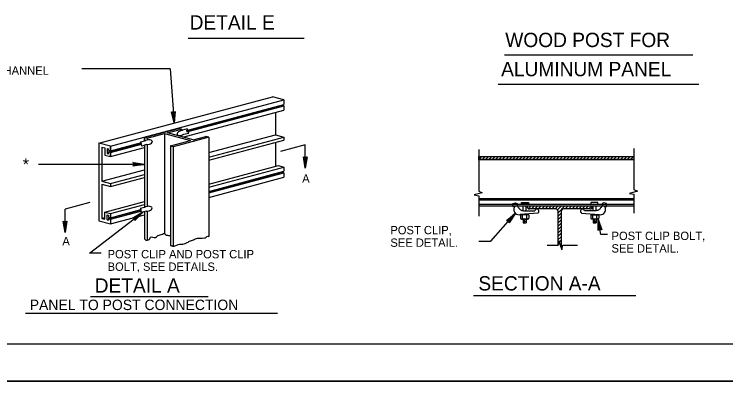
# Model space of a CAD drawing. Extents: x -4 to 901, y -468 to 720.
# Drawn here: x 303.3 to 589.7, y 118.5 to 273.7 of the extents above; entities that cross this region are included whole.
import ezdxf

# ---------------------------------------------------------------- set-up
doc = ezdxf.new("R2010")
doc.units = 0
for name, color, linetype in [('1', 7, 'Continuous'), ('2', 7, 'Continuous'), ('3', 7, 'Continuous'), ('PLT-BNDY', 7, 'Continuous')]:
    doc.layers.add(name, color=color, linetype=linetype)

msp = doc.modelspace()

# ---------------------------------------------------------------- linework, layer by layer
at = {"layer": '1'}
msp.add_lwpolyline([(822.258, 141.027875), (822.258, 705.027875), (36.258, 705.027875), (36.258, 141.027875), (822.258, 141.027875), (822.258, 167.386875), (622.258, 167.386875), (622.258, 232.064375), (822.258, 232.064375), (822.258, 261.027875), (622.258, 261.027875), (622.258, 141.027875), (701.0595, 141.027875), (701.0595, 167.386875), (701.0595, 141.027875), (778.0595, 141.027875), (778.0595, 167.386875), (778.0595, 155.070375), (822.258, 155.070375)], dxfattribs=at)
at = {"layer": '2'}
for p, q in [((365.98, 251.736375), (330.525, 251.736375)), ((365.98, 251.736375), (367.605, 229.949625)), ((337.339, 221.803625), (407.157, 240.509625)), ((341.975, 220.561625), (411.793, 239.267625)), ((411.793, 239.267625), (407.157, 240.511625)), ((411.793, 239.267625), (411.793, 237.425625)), ((371.165, 224.277625), (411.793, 235.163625)), ((372.565, 226.913625), (411.793, 237.425625)), ((372.615, 226.775625), (410.959, 237.049625)), ((372.767, 226.367625), (411.793, 236.825625)), ((410.959, 237.049625), (411.793, 236.825625)), ((411.793, 236.825625), (411.793, 235.163625)), ((408.357, 234.241625), (408.357, 225.209625)), ((363.743, 226.265625), (369.405, 227.783625)), ((370.563, 227.471625), (369.405, 227.783625)), ((370.563, 227.471625), (370.563, 226.749625)), ((372.879, 227.531625), (370.985, 227.011625)), ((373.493, 225.845625), (372.879, 227.531625)), ((355.629, 224.091625), (355.629, 222.595625)), ((356.787, 223.781625), (355.629, 224.091625)), ((363.743, 225.645625), (363.743, 185.465625)), ((371.571, 225.403625), (373.493, 225.845625)), ((381.595, 224.217625), (380.437, 224.527625)), ((381.595, 218.037625), (408.357, 225.209625)), ((381.595, 216.197625), (411.793, 224.289625)), ((408.357, 225.209625), (411.793, 224.289625)), ((411.793, 224.289625), (411.793, 223.047625)), ((341.975, 220.561625), (337.339, 221.803625)), ((337.339, 221.803625), (337.339, 190.603625)), ((341.141, 218.341625), (354.563, 221.937625)), ((341.141, 218.341625), (354.345, 221.875625)), ((341.975, 218.717625), (354.425, 222.053625)), ((341.975, 218.117625), (354.495, 221.471625)), ((341.975, 220.561625), (341.975, 218.717625)), ((341.975, 218.717625), (341.975, 220.559625)), ((354.261, 222.409625), (356.161, 222.907625)), ((354.573, 220.643625), (354.261, 222.409625)), ((356.457, 221.221625), (354.573, 220.643625)), ((355.629, 221.059625), (355.629, 195.795625)), ((367.261, 220.375625), (366.103, 220.685625)), ((381.595, 214.955625), (411.793, 223.047625)), ((408.357, 222.125625), (408.357, 212.435625)), ((420.383, 221.185625), (410.405, 218.511625)), ((420.383, 211.785625), (420.383, 221.185625)), ((338.539, 220.239625), (338.539, 206.501625)), ((338.539, 220.239625), (339.767, 219.909625)), ((339.767, 219.909625), (339.767, 217.047625)), ((340.601, 219.685625), (340.601, 217.687625)), ((340.601, 219.685625), (341.141, 219.541625)), ((340.601, 217.687625), (341.161, 217.837625)), ((340.601, 217.687625), (341.141, 217.543625)), ((341.141, 218.941625), (341.141, 219.541625)), ((341.141, 218.941625), (341.975, 218.717625)), ((341.141, 217.543625), (341.141, 218.341625)), ((341.141, 218.341625), (341.975, 218.117625)), ((341.975, 216.455625), (355.629, 220.113625)), ((341.975, 218.117625), (341.975, 216.455625)), ((341.975, 216.455625), (341.975, 218.117625)), ((490.19325, 219.327875), (490.19325, 202.533875)), ((552.59325, 219.731875), (552.59325, 203.185875)), ((339.767, 217.047625), (341.975, 216.455625)), ((490.19325, 216.407875), (519.02325, 216.407875)), ((490.19325, 215.207875), (519.02325, 215.207875)), ((519.02325, 216.407875), (528.28125, 216.407875)), ((519.02325, 215.207875), (528.28125, 215.207875)), ((528.28125, 216.407875), (552.59325, 216.407875)), ((528.28125, 215.207875), (552.59325, 215.207875)), ((355.629, 213.296125), (312.982, 213.296125)), ((381.595, 205.265625), (409.585, 212.765625)), ((381.595, 204.081625), (411.793, 212.173625)), ((409.585, 212.765625), (411.793, 212.173625)), ((411.793, 212.173625), (411.793, 210.511625)), ((338.539, 206.501625), (355.629, 211.081625)), ((341.975, 205.581625), (355.629, 209.239625)), ((381.595, 202.417625), (411.793, 210.511625)), ((381.595, 202.267625), (410.959, 210.133625)), ((381.595, 201.817625), (411.793, 209.911625)), ((411.793, 209.911625), (410.959, 210.133625)), ((411.793, 209.911625), (411.793, 208.067625)), ((338.539, 206.501625), (341.975, 205.581625)), ((341.975, 204.339625), (355.629, 207.997625)), ((381.595, 199.977625), (411.793, 208.067625)), ((338.539, 205.259625), (341.975, 204.339625)), ((338.539, 205.259625), (338.539, 191.523625)), ((341.975, 205.581625), (341.975, 204.339625)), ((490.19325, 200.651875), (490.19325, 192.405875)), ((552.59325, 201.279875), (552.59325, 193.643875)), ((333.697, 197.957625), (323.719, 195.283625)), ((339.767, 194.057625), (355.629, 198.307625)), ((490.19325, 199.607875), (519.02325, 199.607875)), ((490.19325, 199.007875), (519.02325, 199.007875)), ((519.02325, 199.607875), (528.28125, 199.607875)), ((519.02325, 199.007875), (528.28125, 199.007875)), ((528.28125, 199.607875), (552.59325, 199.607875)), ((528.28125, 199.007875), (552.59325, 199.007875)), ((323.719, 185.883625), (323.719, 195.283625)), ((341.141, 191.427625), (354.395, 194.977625)), ((341.141, 191.427625), (354.379, 194.971625)), ((341.975, 193.465625), (355.629, 197.123625)), ((341.975, 191.803625), (354.241, 195.089625)), ((354.151, 195.635625), (356.051, 196.131625)), ((354.463, 193.867625), (354.151, 195.635625)), ((490.19325, 197.207875), (519.02325, 197.207875)), ((490.19325, 196.607875), (519.02325, 196.607875)), ((508.08125, 194.639875), (508.08125, 196.593875)), ((509.36925, 194.627875), (509.36925, 196.523875)), ((509.60325, 196.415875), (509.60325, 196.535875)), ((509.60325, 196.535875), (536.00325, 196.535875)), ((519.02325, 197.207875), (528.28125, 197.207875)), ((519.02325, 196.607875), (528.28125, 196.607875)), ((528.28125, 197.207875), (552.59325, 197.207875)), ((528.28125, 196.607875), (552.59325, 196.607875)), ((536.00325, 196.535875), (536.00325, 196.415875)), ((536.23925, 194.627875), (536.23925, 196.523875)), ((537.52525, 194.639875), (537.52525, 196.593875)), ((339.767, 194.057625), (341.975, 193.465625)), ((339.767, 191.195625), (339.767, 194.057625)), ((340.601, 190.971625), (340.601, 192.969625)), ((340.601, 192.969625), (341.141, 192.823625)), ((341.141, 192.823625), (341.141, 192.027625)), ((341.141, 192.027625), (341.975, 191.803625)), ((341.975, 191.203625), (354.269, 194.497625)), ((341.975, 193.465625), (341.975, 191.803625)), ((341.975, 189.361625), (355.629, 193.019625)), ((356.347, 194.445625), (354.463, 193.867625)), ((355.629, 194.267625), (355.629, 183.291625)), ((514.00325, 193.653875), (506.93525, 193.087875)), ((507.04525, 193.033875), (507.04525, 191.569875)), ((510.32725, 193.033875), (507.04525, 193.033875)), ((510.20925, 193.119875), (507.16925, 193.119875)), ((507.16925, 193.041875), (507.16925, 193.119875)), ((507.85325, 191.589875), (507.85325, 193.033875)), ((508.24125, 194.637875), (512.85325, 194.599875)), ((509.51925, 191.599875), (509.51925, 193.033875)), ((510.20925, 193.041875), (510.20925, 193.119875)), ((510.32725, 193.033875), (510.32725, 191.577875)), ((531.60325, 193.653875), (538.67325, 193.087875)), ((537.36725, 194.637875), (532.75325, 194.599875)), ((535.28125, 193.033875), (535.28125, 191.577875)), ((535.28125, 193.033875), (538.56125, 193.033875)), ((535.39925, 193.119875), (538.43925, 193.119875)), ((535.39925, 193.041875), (535.39925, 193.119875)), ((536.08925, 191.599875), (536.08925, 193.033875)), ((537.75525, 191.589875), (537.75525, 193.033875)), ((538.43925, 193.041875), (538.43925, 193.119875)), ((538.56125, 193.033875), (538.56125, 191.569875)), ((337.339, 190.603625), (341.975, 189.361625)), ((338.539, 191.523625), (339.767, 191.851625)), ((338.539, 191.523625), (339.767, 191.851625)), ((338.539, 191.523625), (339.767, 191.195625)), ((340.601, 190.971625), (341.161, 191.121625)), ((340.601, 190.971625), (341.141, 190.827625)), ((341.141, 191.427625), (341.141, 190.827625)), ((341.141, 191.427625), (341.975, 191.203625)), ((341.975, 191.203625), (341.975, 189.361625)), ((507.49325, 191.275875), (509.87725, 191.275875)), ((508.08125, 191.179875), (508.08125, 189.683875)), ((508.08125, 190.403875), (509.36925, 190.403875)), ((508.08125, 189.683875), (509.36925, 189.683875)), ((508.44925, 190.881875), (508.80725, 190.881875)), ((508.44925, 189.985875), (508.80725, 189.985875)), ((509.36925, 191.179875), (509.36925, 189.683875)), ((538.11325, 191.275875), (535.72925, 191.275875)), ((536.23925, 191.239875), (536.23925, 189.683875)), ((536.23925, 190.343875), (537.52525, 190.343875)), ((536.23925, 189.683875), (537.52525, 189.683875)), ((536.61325, 190.881875), (537.09525, 190.881875)), ((536.61325, 190.045875), (537.09525, 190.045875)), ((537.52525, 191.299875), (537.52525, 189.683875)), ((539.30925, 185.117875), (538.23725, 191.291875)), ((517.81125, 180.815875), (522.19925, 180.815875)), ((524.02925, 180.815875), (529.96525, 180.815875))]:
    msp.add_line(p, q, dxfattribs=at)
for points in [[(367.827, 234.337625), (367.525, 234.151625), (367.605, 229.949625), (367.827, 234.337625), (368.001, 234.573625), (367.605, 229.949625), (367.087, 234.115625), (366.763, 234.245625), (367.605, 229.949625), (366.539, 234.465625), (366.763, 234.245625)], [(355.629, 222.587625), (355.629, 224.091625), (363.743, 226.265625)], [(375.333, 223.159625), (364.901, 225.955625), (370.563, 227.471625)], [(356.723, 223.763625), (363.743, 225.645625), (374.175, 222.849625)], [(356.723, 223.797625), (356.723, 223.017625)], [(370.563, 225.099625), (370.563, 224.437625)], [(375.333, 223.159625), (380.437, 224.527625)], [(381.595, 224.217625), (375.333, 222.539625)], [(381.595, 224.217625), (381.595, 184.199625)], [(356.723, 221.293625), (356.723, 196.227625)], [(366.103, 220.685625), (374.175, 222.849625)], [(366.103, 220.685625), (366.103, 180.667625)], [(375.333, 222.539625), (367.261, 220.375625)], [(367.261, 220.375625), (367.261, 180.357625)], [(420.931, 216.145625), (420.615, 215.981625), (420.383, 211.785625), (420.931, 216.145625), (421.123, 216.367625), (420.383, 211.785625), (420.177, 215.979625), (419.865, 216.131625), (420.383, 211.785625), (419.655, 216.367625), (419.865, 216.131625)], [(490.21325, 215.207875), (491.41325, 216.407875)], [(491.56925, 215.207875), (492.76925, 216.407875)], [(492.92725, 215.207875), (494.12725, 216.407875)], [(494.28525, 215.207875), (495.48525, 216.407875)], [(495.64325, 215.207875), (496.84325, 216.407875)], [(497.00125, 215.207875), (498.20125, 216.407875)], [(498.35725, 215.207875), (499.55725, 216.407875)], [(499.71525, 215.207875), (500.91525, 216.407875)], [(501.07325, 215.207875), (502.27325, 216.407875)], [(502.43125, 215.207875), (503.63125, 216.407875)], [(503.78925, 215.207875), (504.98925, 216.407875)], [(505.14725, 215.207875), (506.34725, 216.407875)], [(506.50325, 215.207875), (507.70325, 216.407875)], [(507.86125, 215.207875), (509.06125, 216.407875)], [(509.21925, 215.207875), (510.41925, 216.407875)], [(510.57725, 215.207875), (511.77725, 216.407875)], [(511.93525, 215.207875), (513.13525, 216.407875)], [(513.29125, 215.207875), (514.49325, 216.407875)], [(514.64925, 215.207875), (515.84925, 216.407875)], [(516.00725, 215.207875), (517.20725, 216.407875)], [(517.36525, 215.207875), (518.56525, 216.407875)], [(518.72325, 215.207875), (519.92325, 216.407875)], [(520.08125, 215.207875), (521.28125, 216.407875)], [(521.43725, 215.207875), (522.63725, 216.407875)], [(522.79525, 215.207875), (523.99525, 216.407875)], [(524.15325, 215.207875), (525.35325, 216.407875)], [(525.51125, 215.207875), (526.71125, 216.407875)], [(526.86925, 215.207875), (528.06925, 216.407875)], [(528.22525, 215.207875), (529.42725, 216.407875)], [(529.58325, 215.207875), (530.78325, 216.407875)], [(530.94125, 215.207875), (532.14125, 216.407875)], [(532.29925, 215.207875), (533.49925, 216.407875)], [(533.65725, 215.207875), (534.85725, 216.407875)], [(535.01525, 215.207875), (536.21525, 216.407875)], [(536.37125, 215.207875), (537.57125, 216.407875)], [(537.72925, 215.207875), (538.92925, 216.407875)], [(539.08725, 215.207875), (540.28725, 216.407875)], [(540.44525, 215.207875), (541.64525, 216.407875)], [(541.80325, 215.207875), (543.00325, 216.407875)], [(543.16125, 215.207875), (544.36125, 216.407875)], [(544.51725, 215.207875), (545.71725, 216.407875)], [(545.87525, 215.207875), (547.07525, 216.407875)], [(547.23325, 215.207875), (548.43325, 216.407875)], [(548.59125, 215.207875), (549.79125, 216.407875)], [(549.94925, 215.207875), (551.14925, 216.407875)], [(551.30525, 215.207875), (552.50725, 216.407875)], [(351.269, 213.842125), (351.433, 213.526125), (355.629, 213.296125), (351.269, 213.842125), (351.047, 214.034125), (355.629, 213.296125), (351.435, 213.088125), (351.283, 212.776125), (355.629, 213.296125), (351.047, 212.566125), (351.283, 212.776125)], [(490.19325, 202.533875), (491.66725, 201.851875), (488.35925, 200.995875), (490.19325, 200.651875)], [(552.59325, 203.185875), (554.15325, 202.465875), (550.84525, 201.607875), (552.59325, 201.279875)], [(504.16125, 196.033875), (503.91725, 196.891875), (503.97725, 197.503875), (505.01925, 197.809875), (505.69325, 197.565875), (505.69325, 196.585875)], [(541.44525, 196.033875), (541.69125, 196.891875), (541.62925, 197.503875), (540.58925, 197.809875), (539.91525, 197.565875), (539.91525, 196.585875)], [(509.62725, 196.193875), (509.96925, 196.535875)], [(510.22925, 195.435875), (511.32725, 196.535875)], [(519.02325, 195.335875), (510.68325, 195.335875)], [(511.48525, 195.335875), (512.68525, 196.535875)], [(512.84325, 195.335875), (514.04325, 196.535875)], [(514.19925, 195.335875), (515.39925, 196.535875)], [(515.55725, 195.335875), (516.75725, 196.535875)], [(516.91525, 195.335875), (518.11525, 196.535875)], [(518.27325, 195.335875), (519.47325, 196.535875)], [(521.12325, 195.335875), (519.02325, 195.335875)], [(519.63125, 195.335875), (520.83125, 196.535875)], [(520.98725, 195.335875), (522.18725, 196.535875)], [(521.95525, 194.945875), (523.54525, 196.535875)], [(522.20325, 193.835875), (524.90325, 196.535875)], [(528.28125, 195.335875), (524.48325, 195.335875)], [(525.06125, 195.335875), (526.26125, 196.535875)], [(526.41925, 195.335875), (527.61925, 196.535875)], [(527.77725, 195.335875), (528.97725, 196.535875)], [(534.92325, 195.335875), (528.28125, 195.335875)], [(529.13325, 195.335875), (530.33325, 196.535875)], [(530.49125, 195.335875), (531.69125, 196.535875)], [(531.84925, 195.335875), (533.04925, 196.535875)], [(533.20725, 195.335875), (534.40725, 196.535875)], [(534.56525, 195.335875), (535.76525, 196.535875)], [(338.301, 177.521625), (333.501, 177.521625), (355.013, 194.005625)], [(351.221, 191.789625), (351.541, 191.637625), (355.013, 194.005625), (351.221, 191.789625), (350.927, 191.805625), (355.013, 194.005625), (351.811, 191.291625), (351.879, 190.949625), (355.013, 194.005625), (351.819, 190.641625), (351.879, 190.949625)], [(356.723, 194.453625), (356.723, 182.833625)], [(490.27125, 182.351875), (495.07125, 182.351875), (504.95725, 193.631875)], [(501.67325, 190.713875), (502.01725, 190.627875), (504.95725, 193.631875), (501.67325, 190.713875), (501.38125, 190.671875), (504.95725, 193.631875), (502.34925, 190.341875), (502.48325, 190.019875), (504.95725, 193.631875), (502.48525, 189.705875), (502.48325, 190.019875)], [(522.20325, 180.815875), (522.20325, 194.255875)], [(522.20325, 192.477875), (523.40325, 193.677875)], [(522.20325, 191.119875), (523.40325, 192.319875)], [(523.40325, 194.255875), (523.40325, 179.757875)], [(324.265, 190.243625), (323.951, 190.081625), (323.719, 185.883625), (324.265, 190.243625), (324.457, 190.465625), (323.719, 185.883625), (323.511, 190.077625), (323.199, 190.229625), (323.719, 185.883625), (322.991, 190.465625), (323.199, 190.229625)], [(522.20325, 189.763875), (523.40325, 190.963875)], [(522.20325, 188.405875), (523.40325, 189.605875)], [(538.44325, 186.903875), (538.72725, 187.117875), (538.23725, 191.291875), (538.44325, 186.903875), (538.29325, 186.649875), (538.23725, 191.291875), (539.15925, 187.195875), (539.49125, 187.097875), (538.23725, 191.291875), (539.73725, 186.901875), (539.49125, 187.097875)], [(522.20325, 187.047875), (523.40325, 188.247875)], [(522.20325, 185.689875), (523.40325, 186.889875)], [(522.20325, 184.331875), (523.40325, 185.531875)], [(522.20325, 182.975875), (523.40325, 184.175875)], [(541.99125, 185.117875), (539.30925, 185.117875)], [(522.19925, 180.815875), (522.49925, 182.471875), (523.71125, 178.833875), (524.02925, 180.815875)], [(523.40325, 179.757875), (522.49925, 182.471875), (522.20325, 180.815875)], [(522.20325, 181.617875), (522.37925, 181.791875)], [(522.63925, 182.051875), (523.40325, 182.817875)], [(522.97925, 181.033875), (523.40325, 181.459875)], [(523.31725, 180.015875), (523.40325, 180.101875)]]:
    msp.add_lwpolyline(points, dxfattribs=at)
for points in [[(490.19325, 215.207875), (490.19325, 216.407875), (552.59325, 216.407875), (552.59325, 215.207875)], [(507.40925, 197.259875), (507.40925, 197.993875), (510.28725, 197.993875), (510.28725, 197.259875)], [(538.19925, 197.259875), (538.19925, 197.993875), (535.32125, 197.993875), (535.32125, 197.259875)]]:
    msp.add_lwpolyline(points, close=True, dxfattribs=at)
for centre, radius, start, end in [((506.619763, 195.128679), 2.321207, 153.15836389, 226.54434722), ((510.68411, 196.415692), 1.08, 180, 270), ((513.65603, 194.441452), 0.817265, 293.84417222, 168.80884167), ((521.12411, 194.255692), 1.08, 0, 90), ((524.48411, 194.255692), 1.08, 90, 180), ((531.95219, 194.441452), 0.817265, 11.19115833, 246.15582778), ((534.92411, 196.415692), 1.08, 270, 0), ((538.988457, 195.128679), 2.321207, 313.45565278, 26.84163611), ((506.407961, 195.609851), 2.576281, 237.41135, 281.94336389), ((539.200258, 195.609851), 2.576281, 258.05663611, 302.58865), ((507.494411, 191.319542), 0.044385, 180, 270), ((509.878022, 191.319542), 0.044385, 270, 0), ((535.730198, 191.319542), 0.044385, 180, 270), ((538.113809, 191.319542), 0.044385, 270, 0)]:
    msp.add_arc(centre, radius, start, end, dxfattribs=at)
for centre, major_axis, ratio, start_param, end_param in [((370.57391, 225.951205), (1.721758, 0.626669), 0.511999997, 1.1491127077, 5.1340725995), ((357.04723, 222.193916), (-1.80442, -0.318168), 0.511999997, 1.1491127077, 5.1340725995), ((356.937791, 195.419308), (-1.80442, -0.318168), 0.511999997, 1.1491127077, 5.1340725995), ((507.449064, 191.594555), (0.405014, -0.004425), 0.6798527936, 3.2480247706, 6.2831853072), ((508.686298, 191.594597), (0.83222, 0.004467), 0.3359639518, 3.1415926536, 6.2831853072), ((509.923502, 191.60352), (-0.405014, -0.004425), 0.6798527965, 0, 3.0351605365), ((535.684718, 191.60352), (0.405014, -0.004425), 0.6798527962, 3.2480247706, 6.2831853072), ((536.921922, 191.594597), (-0.83222, 0.004467), 0.3359639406, 0, 3.1415926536), ((538.159156, 191.594555), (-0.405014, -0.004425), 0.6798527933, 0, 3.0351605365)]:
    msp.add_ellipse(centre, major_axis=major_axis, ratio=ratio, start_param=start_param, end_param=end_param, dxfattribs=at)
for points in [[(504.54725, 196.175875), (505.00925, 196.513875), (505.63925, 196.537875), (505.94925, 196.243875), (506.31925, 195.739875), (506.69925, 195.311875), (507.09725, 194.933875), (507.51125, 194.779875), (508.24125, 194.641875)], [(541.05925, 196.175875), (540.59925, 196.513875), (539.96925, 196.537875), (539.65725, 196.243875), (539.28925, 195.739875), (538.90925, 195.311875), (538.51125, 194.933875), (538.09725, 194.779875), (537.36725, 194.641875)], [(355.629, 183.291625), (355.965, 183.107625), (356.241, 182.833625), (356.723, 182.833625), (357.801, 183.291625), (358.077, 184.025625), (360.095, 183.841625), (360.921, 184.483625), (361.195, 184.667625), (362.939, 185.217625), (363.743, 185.465625), (363.857, 185.309625), (365.415, 184.667625), (366.149, 184.575625)], [(366.103, 180.667625), (366.517, 180.631625), (366.793, 180.447625), (367.261, 180.357625), (367.893, 180.447625), (368.719, 180.813625), (369.819, 181.181625), (370.553, 181.181625), (372.573, 181.639625), (373.857, 182.373625), (375.417, 182.923625), (376.151, 183.291625), (379.821, 183.657625), (380.187, 183.749625), (380.829, 184.301625), (381.595, 184.199625)]]:
    msp.add_spline(points, degree=3, dxfattribs=at)
at = {"layer": '3'}
for p, q in [((373.3315, 264.091375), (419.9175, 264.091375)), ((500.62825, 257.400375), (576.40825, 257.400375)), ((497.98825, 245.622625), (578.76025, 245.622625)), ((488.08325, 160.495875), (553.42325, 160.495875)), ((333.96225, 160.147625), (381.34025, 160.147625)), ((307.78625, 153.395625), (409.24825, 153.395625))]:
    msp.add_line(p, q, dxfattribs=at)
at = {"layer": 'PLT-BNDY'}
for points in [[(-3.742, 720.027875), (837.258, 720.027875), (837.258, 126.027875), (-3.742, 126.027875)], [(-3.742, 126.027875), (837.258, 126.027875), (837.258, -467.972125), (-3.742, -467.972125)]]:
    msp.add_lwpolyline(points, close=True, dxfattribs=at)

# ---------------------------------------------------------------- texts
at = {"layer": '3'}
for s, height, p in [('DETAIL E', 5.76, (373.85975, 267.551375)), ('WOOD POST FOR', 5.76, (500.90225, 260.492375)), ('EXTRUDED ALUMINUM CHANNEL', 3.359988, (244.5495, 249.348137)), ('ALUMINUM PANEL', 5.76, (499.23625, 248.756625)), ('*', 4.8384, (306.67925, 210.862125)), ('A', 3.359988, (419.157, 205.935625)), ('POST CLIP,', 3.359988, (454.65475, 185.137625)), ('POST CLIP BOLT,', 3.359988, (543.67125, 182.827875)), ('A', 3.359988, (322.633, 180.697625)), ('SEE DETAIL.', 3.359988, (454.65475, 180.097625)), ('SEE DETAIL.', 3.359988, (543.67125, 177.787875)), ('POST CLIP AND POST CLIP', 3.359988, (340.843, 175.463625)), ('BOLT, SEE DETAILS.', 3.359988, (340.843, 170.423625)), ('DETAIL A', 5.76, (335.64425, 161.653625)), ('SECTION A-A', 5.76, (490.06925, 162.511875)), ('PANEL TO POST CONNECTION', 4.2, (309.49625, 154.633625))]:
    msp.add_text(s, height=height, dxfattribs=at).set_placement(p)

doc.saveas('drawing.dxf')
